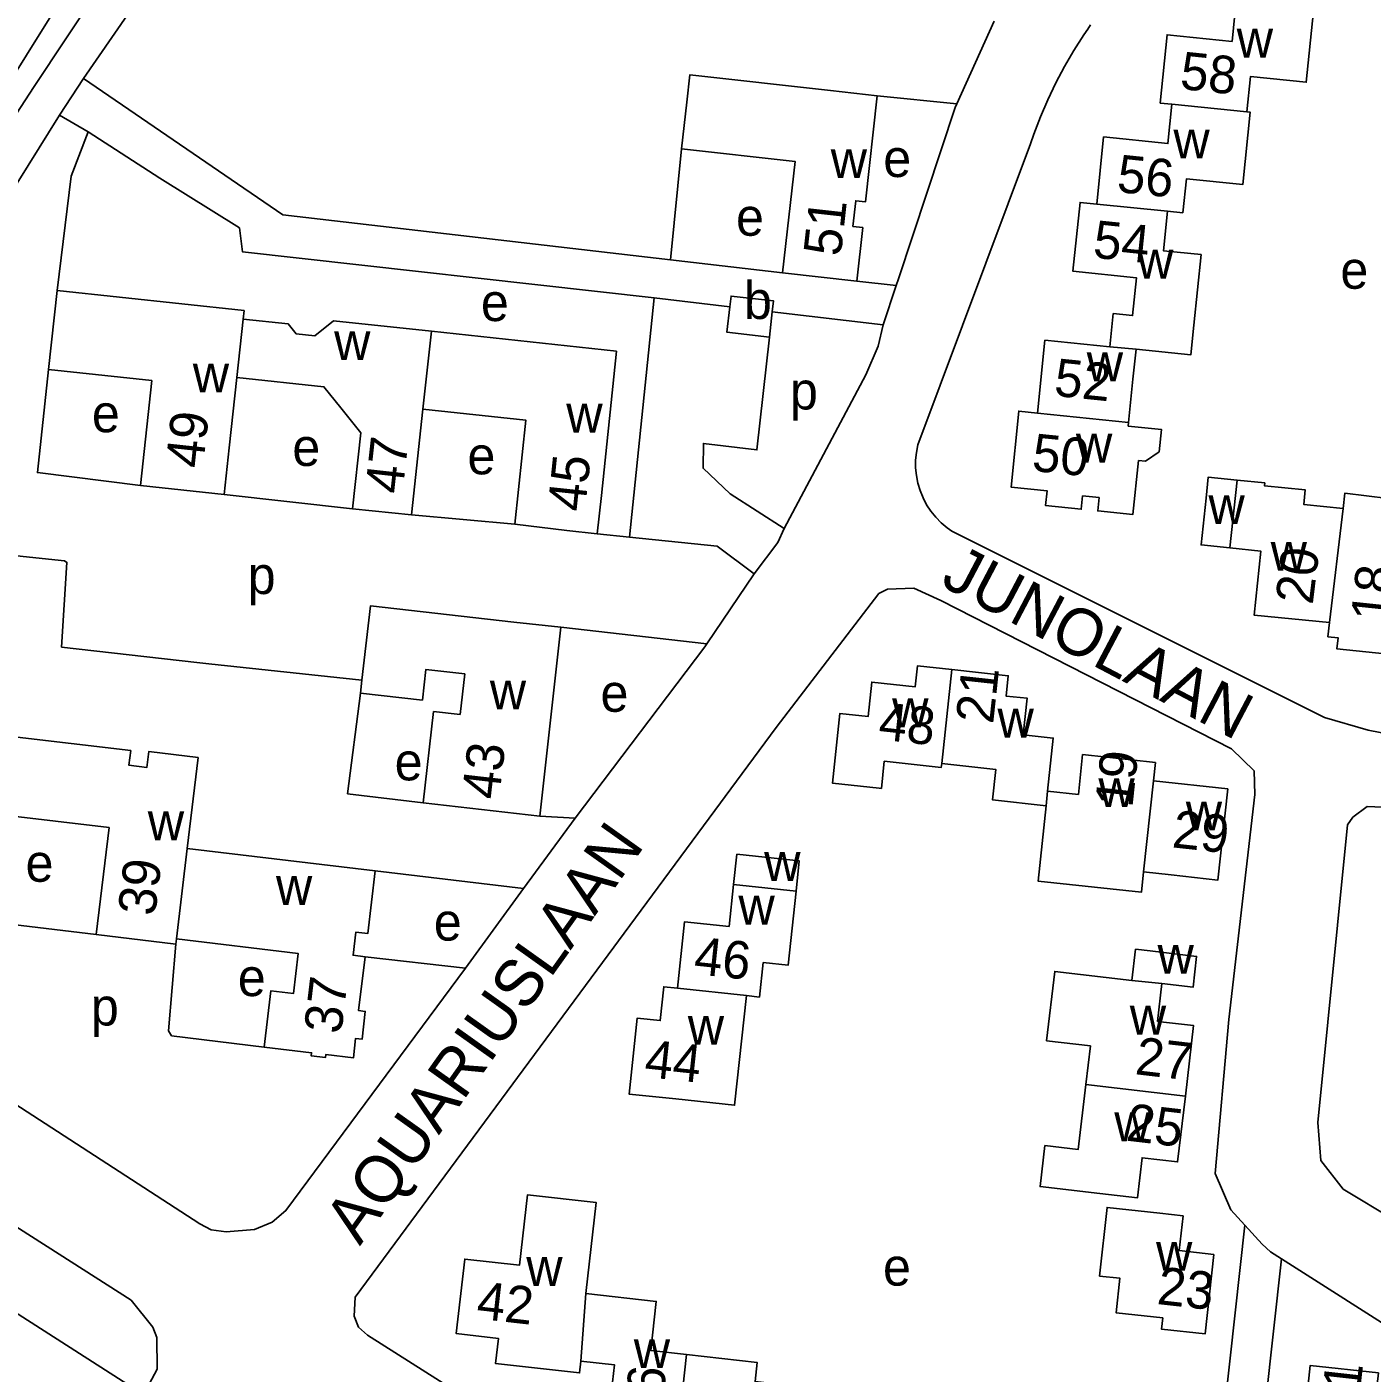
# Model space of a CAD drawing. Extents: x 161936 to 163647, y 386450 to 388633.
# Drawn here: x 162807.2 to 162950.3, y 386841.4 to 386984.7 of the extents above; entities that cross this region are included whole.
import ezdxf

# ---------------------------------------------------------------- set-up
doc = ezdxf.new("R2010")
doc.units = 0
for name, color, linetype in [('BLT_Basislijn', 7, 'Continuous'), ('BLT_Bebouwing', 7, 'Continuous'), ('BLT_Centroide', 7, 'Continuous'), ('BLT_Hoogspanningsmast_en_leidingen', 7, 'Continuous'), ('BLT_Huisnummer', 7, 'Continuous'), ('BLT_Onderverdeling_panden', 7, 'Continuous'), ('BLT_Straatnaam', 7, 'Continuous')]:
    doc.layers.add(name, color=color, linetype=linetype)

msp = doc.modelspace()

# ---------------------------------------------------------------- linework, layer by layer
at = {"layer": 'BLT_Basislijn'}
for p, q in [((162906.15, 386976.47), (162910.12, 386985.26)), ((162920.39, 386984.86), (162920.08, 386984.41)), ((162813.2, 386979.16), (162810.67, 386975.26)), ((162906.15, 386976.47), (162897.69, 386977.32)), ((162810.67, 386975.26), (162782.82, 386930.8)), ((162813.71, 386973.47), (162810.67, 386975.26)), ((162876.86, 386971.68), (162875.69, 386959.85)), ((162913.99, 386972.2), (162902.01, 386940.18)), ((162875.69, 386959.85), (162887.61, 386958.47)), ((162899.69, 386957.13), (162895.5, 386957.59)), ((162898.32, 386952.96), (162899.69, 386957.13)), ((162871.33, 386930.34), (162873.93, 386955.83)), ((162873.93, 386955.83), (162882, 386954.86)), ((162898.32, 386952.96), (162886.51, 386954.33)), ((162828.17, 386934.88), (162841.85, 386933.38)), ((162848.1, 386932.71), (162859.11, 386931.73)), ((162871.33, 386930.34), (162867.88, 386930.7)), ((162884.6, 386926.46), (162879.55, 386919)), ((162879.55, 386919), (162864.02, 386920.76)), ((162842.84, 386915.12), (162826.53, 386916.88)), ((162969.16, 386906.11), (162949.93, 386909.8)), ((162865.54, 386900.45), (162860.05, 386892.96)), ((162865.54, 386900.45), (162861.77, 386900.67)), ((162860.05, 386892.96), (162844.26, 386894.83)), ((162853.85, 386884.48), (162860.05, 386892.96)), ((162853.85, 386884.48), (162843.17, 386885.7)), ((162931.98, 386813.46), (162936.8, 386857.14)), ((162940.71, 386853.55), (162933.41, 386788.33))]:
    msp.add_line(p, q, dxfattribs=at)
for points in [[(162994.68, 387190.62), (162985.54, 387189.48), (162980.86, 387188.14), (162974.88, 387184.86), (162966.28, 387177.45), (162938.28, 387149.79), (162903.24, 387114.51), (162892.82, 387104.85), (162888.74, 387100), (162884.14, 387095.5), (162876.92, 387087.93), (162850.19, 387044.96), (162849.96, 387039.13), (162825.52, 387004.78), (162807.9, 386978.22), (162790.61, 386951.66), (162774.68, 386925.41), (162767.27, 386912.48), (162763.63, 386897.48)], [(162860.48, 387067.36), (162844.14, 387041.61), (162844.89, 387040.86), (162842.45, 387036.54), (162841.51, 387036.91), (162818.24, 387000), (162809.72, 386985.81), (162799.34, 386969.19)], [(162813.2, 386979.16), (162845.68, 387026.17), (162853.25, 387036.08)], [(162920.08, 386984.41), (162919.66, 386983.8), (162918.6, 386982.14), (162917.61, 386980.43), (162916.68, 386978.69), (162915.83, 386976.91), (162915.05, 386975.09), (162914.35, 386973.25), (162913.99, 386972.2)], [(162813.2, 386979.16), (162834.42, 386964.64), (162875.69, 386959.85)], [(162899.69, 386957.13), (162899.93, 386957.86), (162905.97, 386976.06), (162906.15, 386976.47)], [(162810.4, 386956.6), (162811.9, 386968.78), (162813.71, 386973.47)], [(162873.93, 386955.83), (162830.13, 386960.7), (162829.82, 386963.27), (162821.33, 386968.56), (162813.71, 386973.47)], [(162887.79, 386931.29), (162896.45, 386947.63), (162897.77, 386950.68), (162898.32, 386952.96)], [(162886.21, 386951.64), (162884.87, 386939.64), (162879.18, 386940.32), (162879.15, 386937.69), (162882.02, 386934.98), (162887.79, 386931.29)], [(162809.5, 386948.2), (162808.31, 386937.22), (162819.27, 386935.84)], [(162902.01, 386940.18), (162901.85, 386939.37), (162901.77, 386938.55), (162901.77, 386937.72), (162901.85, 386936.9), (162902.01, 386936.09), (162902.24, 386935.3), (162902.56, 386934.53), (162902.94, 386933.8), (162903.4, 386933.11), (162903.91, 386932.47), (162904.49, 386931.88), (162905.12, 386931.35), (162905.63, 386930.99)], [(162884.6, 386926.46), (162887.11, 386929.8), (162887.79, 386931.29)], [(162826.53, 386916.88), (162825.28, 386917.02), (162810.88, 386918.66), (162811.45, 386927.66), (162811.19, 386927.82), (162782.82, 386930.8)], [(162884.6, 386926.46), (162880.65, 386929.38), (162871.33, 386930.34)], [(162949.93, 386909.8), (162945.27, 386911.16), (162905.63, 386930.99)], [(162936.8, 386857.14), (162935.32, 386858.78), (162933.64, 386862.63), (162935.1, 386879.01), (162937.86, 386902.98), (162937.81, 386905.48), (162935.4, 386907.84), (162904.46, 386923.62), (162901.57, 386924.93), (162898.79, 386924.8), (162897.86, 386924.36), (162886.94, 386910.11), (162842.13, 386849.46), (162842.02, 386847.45), (162842.46, 386846.29), (162843.42, 386845.43), (162927.11, 386792.36), (162929.58, 386790.79)], [(162879.55, 386919), (162879.33, 386918.67), (162865.54, 386900.45)], [(162842.69, 386913.75), (162841.32, 386903.04), (162849.36, 386902.08)], [(162986.1, 386836.47), (162958.12, 386854.43), (162947.27, 386860.98), (162944.88, 386864), (162944.56, 386868.07), (162947.74, 386899.75), (162948.3, 386900.54), (162949.81, 386901.69), (162953.09, 386901.56), (162999.21, 386892.86), (163006.25, 386891.06), (163020.61, 386884.78), (163024.87, 386882.62), (163034.26, 386876.35), (163039.81, 386871.96), (163047.72, 386863.41), (163054.24, 386853.74)], [(162804.32, 386899.21), (162802.99, 386889.44), (162814.57, 386888.06)], [(162853.85, 386884.48), (162834.75, 386858.69), (162833.3, 386857.45), (162831.4, 386856.66), (162828.38, 386856.44), (162826.79, 386856.65), (162825.58, 386857.29), (162767.1, 386895.21)], [(162823.05, 386887.05), (162822.26, 386877.83), (162822.58, 386877.29), (162832.42, 386876.09)], [(162812.79, 386827.68), (162817.86, 386835.81), (162821.06, 386841.79), (162821, 386845.16), (162820.58, 386846.26), (162818.29, 386849.14), (162764.7, 386883.35)], [(162940.71, 386853.55), (162939.53, 386854.3), (162938.64, 386855.1), (162936.8, 386857.14)], [(162940.71, 386853.55), (162982.76, 386826.76), (162995.17, 386821.26), (163006.15, 386818.25), (163030.8, 386815.23), (163038.87, 386815.62), (163043.97, 386816.9), (163048.01, 386818.74), (163065.99, 386830.74), (163069.02, 386830.52), (163069.91, 386829.65), (163093.78, 386793.5), (163093.85, 386793.02), (163019.85, 386743.74), (163013.25, 386739.82), (163009.49, 386739.71), (163008.7, 386739.9), (162933.41, 386788.33)]]:
    msp.add_lwpolyline(points, dxfattribs=at)
at = {"layer": 'BLT_Bebouwing'}
for p, q in [((162929.04, 386976.43), (162927.78, 386976.55)), ((162928.57, 386965.03), (162930.22, 386964.86)), ((162895.5, 386957.59), (162887.61, 386958.47)), ((162809.5, 386948.2), (162810.4, 386956.6)), ((162886.21, 386951.64), (162886.51, 386954.33)), ((162849.31, 386943.98), (162848.1, 386932.71)), ((162924.39, 386942.18), (162924.43, 386942.57)), ((162828.17, 386934.88), (162819.27, 386935.84)), ((162848.1, 386932.71), (162841.85, 386933.38)), ((162842.84, 386915.12), (162842.69, 386913.75)), ((162850.44, 386911.8), (162849.36, 386902.08)), ((162825.4, 386906.92), (162824.25, 386897.21)), ((162927.29, 386906.37), (162927.08, 386904.41)), ((162849.36, 386902.08), (162861.77, 386900.67)), ((162824.25, 386897.21), (162844.26, 386894.83)), ((162823.05, 386887.05), (162814.57, 386888.06)), ((162823.05, 386887.05), (162823.11, 386887.6)), ((162883.76, 386881.56), (162885.15, 386881.41))]:
    msp.add_line(p, q, dxfattribs=at)
for points in [[(162935.86, 386987.12), (162935.45, 386983.11), (162928.53, 386983.82), (162927.78, 386976.55)], [(162937, 386975.61), (162937.39, 386979.37), (162943.33, 386978.76), (162944.11, 386986.32), (162943.84, 386986.34)], [(162876.86, 386971.68), (162877.41, 386976.65), (162877.73, 386979.55), (162892.72, 386977.88), (162897.69, 386977.32)], [(162897.69, 386977.32), (162896.43, 386966.03), (162895.4, 386966.15), (162895.09, 386963.42), (162896.14, 386963.3), (162895.5, 386957.59)], [(162929.04, 386976.43), (162928.61, 386972.24), (162921.77, 386972.94), (162921.04, 386965.8)], [(162930.22, 386964.86), (162930.6, 386968.5), (162936.58, 386967.88), (162937.37, 386975.57), (162937, 386975.61)], [(162887.61, 386958.47), (162888.93, 386970.34), (162876.86, 386971.68)], [(162921.04, 386965.8), (162919.26, 386965.98), (162918.51, 386958.65), (162925.27, 386957.95), (162924.86, 386953.93), (162922.8, 386954.14), (162922.44, 386950.6)], [(162925.22, 386950.35), (162931.05, 386949.75), (162931.38, 386952.91), (162932.14, 386960.42), (162928.14, 386960.83), (162928.57, 386965.03)], [(162810.4, 386956.6), (162830.3, 386954.46), (162830.2, 386953.55)], [(162886.51, 386954.33), (162886.65, 386955.5), (162882.13, 386956.01), (162882, 386954.86)], [(162882, 386954.86), (162881.69, 386952.15), (162886.21, 386951.64)], [(162830.2, 386953.55), (162834.99, 386953.04), (162835.83, 386952), (162837.82, 386951.78), (162839.8, 386953.38), (162850.23, 386952.26)], [(162850.23, 386952.26), (162869.93, 386950.14), (162868.32, 386934.8), (162867.88, 386930.7)], [(162922.44, 386950.6), (162915.53, 386951.3), (162914.74, 386943.56)], [(162924.43, 386942.57), (162924.9, 386947.16), (162925.22, 386950.35)], [(162819.27, 386935.84), (162820.47, 386947.02), (162809.5, 386948.2)], [(162829.51, 386947.34), (162828.71, 386939.86), (162828.17, 386934.88)], [(162841.85, 386933.38), (162842.72, 386941.47), (162840.58, 386944.12), (162838.79, 386946.35), (162829.51, 386947.34)], [(162859.11, 386931.73), (162860.3, 386942.8), (162849.31, 386943.98)], [(162914.74, 386943.56), (162912.74, 386943.77), (162911.92, 386935.68), (162915.75, 386935.29), (162915.59, 386933.72), (162919.39, 386933.33), (162919.54, 386934.74), (162921.29, 386934.56), (162921.14, 386933.15), (162924.9, 386932.77), (162925.49, 386938.5), (162926.22, 386938.43), (162927.68, 386939.45), (162927.92, 386941.82), (162924.39, 386942.18)], [(162935.22, 386929.21), (162932.15, 386929.53), (162932.67, 386934.5), (162932.9, 386936.75), (162935.98, 386936.43)], [(162935.98, 386936.43), (162938.92, 386936.12), (162938.89, 386935.83), (162943.23, 386935.38), (162943.07, 386933.84), (162947.26, 386933.4)], [(162958.28, 386929.2), (162958.6, 386932.27), (162955.53, 386932.59), (162955.33, 386930.65), (162951.65, 386931.09), (162952.07, 386934.48), (162947.46, 386935.05), (162947.26, 386933.4)], [(162867.88, 386930.7), (162864.65, 386931.05), (162859.11, 386931.73)], [(162945.8, 386921.28), (162937.78, 386922.05), (162938.5, 386928.87), (162935.22, 386929.21)], [(162957.51, 386925.22), (162954.4, 386925.54), (162953.86, 386920.29), (162952.31, 386920.45), (162952.17, 386919.08), (162951.87, 386919.11), (162951.75, 386917.92), (162946.61, 386918.45), (162946.73, 386919.64), (162945.64, 386919.76), (162945.8, 386921.28)], [(162864.02, 386920.76), (162859.01, 386921.31), (162843.74, 386923.03), (162842.84, 386915.12)], [(162861.77, 386900.67), (162864.02, 386920.76)], [(162842.69, 386913.75), (162849.28, 386913.01), (162849.63, 386916.25), (162853.78, 386915.8), (162853.29, 386911.49), (162850.44, 386911.8)], [(162904.54, 386906.25), (162904.5, 386905.85), (162898.43, 386906.5), (162898.12, 386903.62), (162897.88, 386903.65), (162892.91, 386904.18), (162893.71, 386911.59), (162896.7, 386911.26), (162897.1, 386914.93), (162901.72, 386914.43), (162901.96, 386916.65), (162905.62, 386916.25)], [(162915.8, 386903.32), (162916.41, 386908.96), (162913.22, 386909.31), (162913.64, 386913.2), (162911.39, 386913.44), (162911.62, 386915.61), (162905.62, 386916.25)], [(162805.54, 386909.14), (162818.24, 386907.63), (162818.05, 386906.07), (162819.96, 386905.84), (162820.16, 386907.54), (162825.4, 386906.92)], [(162927.29, 386906.37), (162919.54, 386907.21), (162919.09, 386902.97), (162915.8, 386903.32)], [(162915.67, 386901.76), (162909.95, 386902.38), (162910.3, 386905.63), (162904.54, 386906.25)], [(162927.08, 386904.41), (162934.99, 386903.56), (162933.94, 386893.86), (162928.97, 386894.4), (162926.03, 386894.72)], [(162926.03, 386894.72), (162925.8, 386892.56), (162914.8, 386893.75), (162915.67, 386901.76)], [(162814.57, 386888.06), (162815.93, 386899.44), (162804.51, 386900.8)], [(162882.39, 386893.38), (162882.74, 386896.6), (162887.71, 386896.07), (162889.39, 386895.89), (162889.04, 386892.67)], [(162844.26, 386894.83), (162843.46, 386888.16), (162842.19, 386888.31), (162841.89, 386885.85), (162843.17, 386885.7)], [(162876.42, 386882.35), (162877.18, 386889.43), (162881.92, 386888.93), (162882.39, 386893.38)], [(162889.04, 386892.67), (162888.2, 386884.8), (162885.55, 386885.08), (162885.15, 386881.41)], [(162832.42, 386876.09), (162833.13, 386882.06), (162835.54, 386881.78), (162836.05, 386886.06), (162823.11, 386887.6)], [(162843.17, 386885.7), (162842.48, 386879.96), (162843.2, 386879.88), (162842.85, 386876.92), (162842.17, 386877), (162841.93, 386874.93), (162838.99, 386875.28), (162838.95, 386874.97), (162837.44, 386875.15), (162837.48, 386875.49), (162832.42, 386876.09)], [(162924.78, 386883.18), (162925.17, 386886.5), (162926.71, 386886.32), (162931.67, 386885.74), (162931.29, 386882.46), (162927.98, 386882.85)], [(162919.88, 386872.11), (162920.36, 386876.21), (162915.71, 386876.76), (162916.57, 386884.13), (162924.78, 386883.18)], [(162883.76, 386881.56), (162882.5, 386869.89), (162876.25, 386870.56), (162871.27, 386871.09), (162872.14, 386879.17), (162874.58, 386878.9), (162874.96, 386882.5), (162876.42, 386882.35)], [(162927.98, 386882.85), (162927.51, 386878.82), (162931.35, 386878.37), (162930.47, 386870.87)], [(162930.47, 386870.87), (162929.65, 386863.86), (162925.87, 386864.31), (162925.37, 386860.03), (162921.37, 386860.5), (162915.02, 386861.24), (162915.53, 386865.61), (162919.07, 386865.19), (162919.88, 386872.11)], [(162866.14, 386842.66), (162866, 386841.4), (162857.07, 386842.41), (162857.37, 386845.08), (162852.88, 386845.59), (162853.78, 386853.52), (162859.6, 386852.86), (162860.45, 386860.36), (162867.78, 386859.53), (162866.68, 386849.86)], [(162930.23, 386858.14), (162929.81, 386854.42), (162933.5, 386854.01), (162932.57, 386845.55), (162927.93, 386846.07), (162928.07, 386847.26), (162923.1, 386847.81), (162923.51, 386851.48), (162921.34, 386851.72), (162922.14, 386859.03), (162927.77, 386858.41), (162930.23, 386858.14)], [(162866.68, 386849.86), (162874.17, 386849.01), (162873.58, 386843.8), (162877.39, 386843.36)], [(162876.33, 386834.04), (162868.88, 386834.89), (162869.72, 386842.26), (162866.14, 386842.66)], [(162877.39, 386843.36), (162884.91, 386842.51), (162884.68, 386840.48), (162888.73, 386840.02), (162888.36, 386836.79), (162888.13, 386834.77)], [(162950.51, 386828.84), (162945.78, 386829.36), (162945.46, 386826.89), (162940.49, 386827.44), (162941.66, 386837.99), (162943.28, 386837.81), (162943.77, 386842.21), (162951.02, 386841.41), (162950.64, 386838.01), (162951.52, 386837.91)]]:
    msp.add_lwpolyline(points, dxfattribs=at)
at = {"layer": 'BLT_Hoogspanningsmast_en_leidingen'}
msp.add_line((162756.36, 386879.56), (163001.94, 386722.51), dxfattribs=at)
at = {"layer": 'BLT_Onderverdeling_panden'}
for p, q in [((162937, 386975.61), (162929.04, 386976.43)), ((162921.04, 386965.8), (162928.57, 386965.03)), ((162830.2, 386953.55), (162829.51, 386947.34)), ((162850.23, 386952.26), (162849.31, 386943.98)), ((162922.44, 386950.6), (162925.22, 386950.35)), ((162914.74, 386943.56), (162924.43, 386942.57)), ((162935.98, 386936.43), (162935.22, 386929.21)), ((162947.26, 386933.4), (162945.8, 386921.28)), ((162904.54, 386906.25), (162905.62, 386916.25)), ((162927.08, 386904.41), (162926.03, 386894.72)), ((162915.8, 386903.32), (162915.67, 386901.76)), ((162823.11, 386887.6), (162824.25, 386897.21)), ((162882.39, 386893.38), (162889.04, 386892.67)), ((162876.42, 386882.35), (162883.76, 386881.56)), ((162924.78, 386883.18), (162927.98, 386882.85)), ((162919.88, 386872.11), (162930.47, 386870.87)), ((162866.68, 386849.86), (162866.14, 386842.66)), ((162876.33, 386834.04), (162877.39, 386843.36))]:
    msp.add_line(p, q, dxfattribs=at)

# ---------------------------------------------------------------- texts
at = {"layer": 'BLT_Centroide'}
for s, p in [('w', (162935.94, 386981.38)), ('w', (162929.2, 386970.66)), ('w', (162892.73, 386968.56)), ('e', (162898.32, 386968.68)), ('e', (162882.65, 386962.43)), ('w', (162925.33, 386957.86)), ('e', (162946.97, 386956.79)), ('b', (162883.5, 386953.57)), ('e', (162855.5, 386953.35)), ('w', (162839.88, 386949.19)), ('w', (162919.98, 386946.94)), ('w', (162824.84, 386945.75)), ('p', (162888.39, 386943.94)), ('e', (162814.1, 386941.52)), ('w', (162864.59, 386941.47)), ('w', (162918.83, 386938.28)), ('e', (162835.43, 386937.93)), ('e', (162854.07, 386937.04)), ('w', (162932.93, 386931.74)), ('w', (162939.55, 386926.78)), ('p', (162830.68, 386924.3)), ('w', (162856.45, 386912.02)), ('e', (162868.23, 386911.77)), ('w', (162899.27, 386910.12)), ('w', (162910.48, 386909.02)), ('e', (162846.32, 386904.47)), ('w', (162921.22, 386901.62)), ('w', (162820.05, 386898.09)), ('w', (162930.52, 386899.14)), ('e', (162807.04, 386893.68)), ('w', (162885.65, 386893.76)), ('w', (162833.69, 386891.22)), ('w', (162882.91, 386889.12)), ('e', (162850.49, 386887.42)), ('w', (162927.51, 386883.88)), ('e', (162829.63, 386881.51)), ('p', (162813.99, 386878.38)), ('w', (162924.56, 386877.41)), ('w', (162877.52, 386876.33)), ('w', (162922.91, 386866.06)), ('w', (162927.35, 386852.28)), ('w', (162860.33, 386850.67)), ('e', (162898.29, 386850.7)), ('w', (162871.77, 386841.92))]:
    msp.add_text(s, height=4, dxfattribs=at).set_placement(p)
at = {"layer": 'BLT_Huisnummer'}
for s, rotation, p in [('58', 354.159, (162929.81, 386978.06)), ('56', 354.1548, (162923.09, 386967.1)), ('51', 83.6364, (162893.79, 386960.15)), ('54', 354.1586, (162920.55, 386960.11)), ('52', 354.1635, (162916.41, 386945.41)), ('49', 83.8631, (162825.92, 386937.6)), ('50', 354.1581, (162914.05, 386937.42)), ('47', 83.6628, (162847.15, 386934.87)), ('45', 84.0052, (162866.57, 386932.98)), ('20', 83.0563, (162944.02, 386923.09)), ('18', 84.041, (162952.05, 386921.26)), ('21', 83.8361, (162910.01, 386910.4)), ('48', 353.8288, (162897.71, 386908.83)), ('43', 83.4356, (162857.43, 386902.34)), ('19', 83.8343, (162924.83, 386901.49)), ('29', 353.8218, (162928.97, 386897.35)), ('39', 83.2066, (162820.82, 386889.96)), ('46', 353.8789, (162878.07, 386883.87)), ('37', 83.203, (162840.63, 386877.4)), ('44', 353.8812, (162872.81, 386872.92)), ('27', 353.3306, (162925.03, 386873.21)), ('25', 353.3369, (162924.07, 386866.14)), ('23', 353.6815, (162927.36, 386848.75)), ('42', 353.5155, (162854.94, 386847.2)), ('26', 83.5242, (162874.59, 386835.99)), ('21', 83.666, (162948.73, 386836.37))]:
    msp.add_text(s, height=4, rotation=rotation, dxfattribs=at).set_placement(p)
at = {"layer": 'BLT_Straatnaam'}
for s, rotation, p in [('JUNOLAAN', 332.2582, (162904.27, 386925.29)), ('AQUARIUSLAAN', 54.56, (162842.62, 386854.86))]:
    msp.add_text(s, height=5, rotation=rotation, dxfattribs=at).set_placement(p)

doc.saveas('drawing.dxf')
